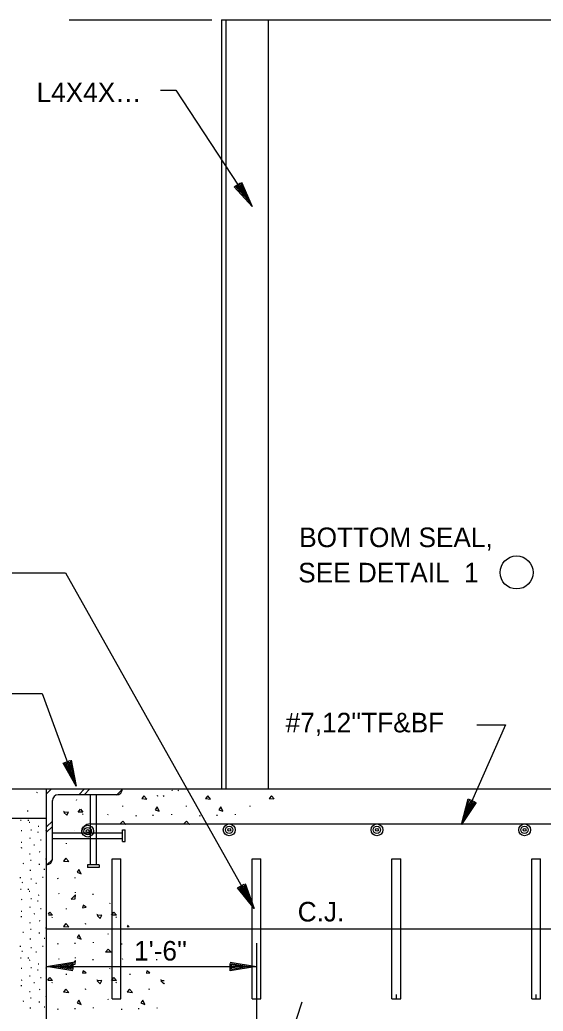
# Model space of a CAD drawing. Extents: x 0 to 320, y -4 to 473.
# Drawn here: x 22.92 to 26.66, y 15.08 to 22.17 of the extents above; entities that cross this region are included whole.
import ezdxf

# ---------------------------------------------------------------- set-up
doc = ezdxf.new("R2010")
doc.units = 0
for name, color, linetype in [('Level 10', 7, 'Continuous'), ('Level 2', 7, 'Continuous'), ('Level 25', 7, 'Continuous'), ('Level 3', 7, 'Continuous'), ('Level 44', 7, 'Continuous'), ('Level 50', 7, 'Continuous')]:
    doc.layers.add(name, color=color, linetype=linetype)

msp = doc.modelspace()

# ---------------------------------------------------------------- linework, layer by layer
at = {"layer": 'Level 10'}
for p, q in [((23.3282, 16.5926), (23.3305, 16.5975)), ((23.9093, 16.6204), (23.9065, 16.6259)), ((23.9538, 16.6204), (23.9509, 16.6259)), ((23.2382, 16.5126), (23.2387, 16.5171)), ((23.6587, 16.5478), (23.6582, 16.5529)), ((24.1142, 16.5478), (24.1138, 16.5529)), ((24.5697, 16.5478), (24.5693, 16.5529)), ((23.3713, 16.4917), (23.3744, 16.4969)), ((23.5527, 16.4893), (23.5536, 16.494)), ((23.7556, 16.4769), (23.7539, 16.4832)), ((23.8769, 16.4819), (23.8769, 16.4882)), ((24.0082, 16.4893), (24.0091, 16.494)), ((24.2112, 16.4769), (24.2094, 16.4832)), ((24.3324, 16.4819), (24.3324, 16.4882)), ((24.4638, 16.4893), (24.4646, 16.494)), ((23.3167, 16.375), (23.3167, 16.3755)), ((23.2558, 16.2809), (23.2567, 16.2869)), ((23.197, 16.0298), (23.1952, 16.0361)), ((23.3183, 16.0348), (23.3183, 16.0411)), ((23.2033, 15.922), (23.2015, 15.9265)), ((23.3204, 15.9312), (23.3204, 15.937)), ((23.4458, 15.9177), (23.4458, 15.924)), ((23.2558, 15.8133), (23.2567, 15.8193)), ((23.5667, 15.8552), (23.569, 15.8601)), ((23.1542, 15.7544), (23.1573, 15.7596)), ((23.4767, 15.7752), (23.4771, 15.7798)), ((23.6097, 15.7544), (23.6128, 15.7596)), ((23.3951, 15.7057), (23.3923, 15.7112)), ((23.5556, 15.6331), (23.5551, 15.6382)), ((23.197, 15.5622), (23.1952, 15.5685)), ((23.3183, 15.5672), (23.3183, 15.5735)), ((23.4496, 15.5746), (23.4504, 15.5793)), ((23.6525, 15.5622), (23.6508, 15.5685)), ((23.2033, 15.4544), (23.2015, 15.4589)), ((23.3204, 15.4636), (23.3204, 15.4694)), ((23.4458, 15.4501), (23.4458, 15.4564)), ((23.6588, 15.4544), (23.657, 15.4589)), ((23.9013, 15.4501), (23.9013, 15.4564)), ((23.5667, 15.3876), (23.569, 15.3925)), ((23.2558, 15.3457), (23.2567, 15.3517)), ((23.4767, 15.3076), (23.4771, 15.3122)), ((23.7113, 15.3457), (23.7122, 15.3517)), ((23.9322, 15.3076), (23.9326, 15.3122)), ((23.1542, 15.2868), (23.1573, 15.292)), ((23.3951, 15.2381), (23.3923, 15.2436)), ((23.6097, 15.2868), (23.6128, 15.292)), ((23.8507, 15.2381), (23.8478, 15.2436)), ((23.5556, 15.1654), (23.5551, 15.1706)), ((23.197, 15.0946), (23.1952, 15.1009)), ((23.3183, 15.0996), (23.3183, 15.1059)), ((23.4496, 15.107), (23.4504, 15.1117)), ((23.6525, 15.0946), (23.6508, 15.1009)), ((23.7738, 15.0996), (23.7738, 15.1059)), ((23.9051, 15.107), (23.906, 15.1117))]:
    msp.add_line(p, q, dxfattribs=at)
for points in [[(23.9293, 21.6715), (24.0386, 21.6715), (24.584, 20.8394)], [(24.0083, 16.6662), (24.0115, 16.6634), (24.013, 16.6662)], [(24.0528, 16.6662), (24.0559, 16.6634), (24.0574, 16.6662)], [(24.7401, 16.6038), (24.7214, 16.6254), (24.7048, 16.6057), (24.7377, 16.6021)], [(23.1274, 15.7787), (23.1383, 15.7931), (23.1571, 15.7717), (23.1274, 15.771)], [(23.6978, 15.6995), (23.6907, 15.691), (23.7048, 15.6894)], [(23.1235, 15.3059), (23.1383, 15.3254), (23.1571, 15.3041), (23.1235, 15.3033)], [(23.9538, 15.3025), (23.9307, 15.3009)], [(23.9307, 15.3009), (23.9528, 15.2811), (23.9563, 15.2876)]]:
    msp.add_lwpolyline(points, dxfattribs=at)
for points in [[(23.8309, 16.6016), (23.8103, 16.6254), (23.7938, 16.6057)], [(24.2865, 16.6016), (24.2658, 16.6254), (24.2493, 16.6057)], [(23.3386, 16.5082), (23.3553, 16.5304), (23.3742, 16.509)], [(23.8904, 16.5257), (23.9189, 16.5146), (23.9039, 16.5454)], [(24.3459, 16.5257), (24.3744, 16.5146), (24.3594, 16.5454)], [(23.2367, 16.5058), (23.2589, 16.486), (23.2707, 16.5082)], [(23.6382, 16.4227), (23.658, 16.4441), (23.6793, 16.4204)], [(24.0938, 16.4227), (24.1136, 16.4441), (24.1348, 16.4204)], [(23.2723, 16.1545), (23.2517, 16.1783), (23.2351, 16.1586)], [(23.3318, 16.0786), (23.3602, 16.0675), (23.3452, 16.0983)], [(23.3189, 15.8877), (23.3204, 15.9156), (23.2896, 15.8854)], [(23.3717, 15.8242), (23.397, 15.8274), (23.3758, 15.8417)], [(23.4751, 15.7685), (23.4973, 15.7487), (23.5092, 15.7709)], [(23.577, 15.7709), (23.5938, 15.7931), (23.6126, 15.7717)], [(23.2723, 15.6869), (23.2517, 15.7107), (23.2351, 15.691)], [(23.3318, 15.611), (23.3602, 15.5999), (23.3452, 15.6307)], [(23.5351, 15.5079), (23.5549, 15.5294), (23.5762, 15.5057)], [(23.3189, 15.4201), (23.3204, 15.4479), (23.2896, 15.4178)], [(23.3717, 15.3566), (23.397, 15.3598), (23.3758, 15.3741)], [(23.577, 15.3033), (23.5938, 15.3254), (23.6126, 15.3041)], [(23.8272, 15.3566), (23.8525, 15.3598), (23.8313, 15.3741)], [(23.2723, 15.2193), (23.2517, 15.2431), (23.2351, 15.2234)], [(23.4751, 15.3009), (23.4973, 15.2811), (23.5092, 15.3033)], [(23.7278, 15.2193), (23.7072, 15.2431), (23.6907, 15.2234)], [(23.3318, 15.1434), (23.3602, 15.1323), (23.3452, 15.1631)], [(23.7873, 15.1434), (23.8158, 15.1323), (23.8008, 15.1631)]]:
    msp.add_lwpolyline(points, close=True, dxfattribs=at)
at = {"layer": 'Level 2'}
for p, q in [((24.3641, 22.1736), (24.3641, 16.6736)), ((24.3641, 22.1736), (27.3641, 22.1736)), ((24.3953, 22.1736), (24.3953, 16.6736)), ((24.6974, 22.1736), (24.6974, 16.6736)), ((23.1141, 16.6379), (23.1497, 16.6736)), ((23.1141, 16.1319), (23.1141, 16.6736)), ((23.1141, 16.6736), (23.6558, 16.6736)), ((23.3438, 16.6319), (23.3854, 16.6736)), ((23.3815, 16.6319), (23.4231, 16.6736)), ((23.6172, 16.6319), (23.6589, 16.6736)), ((23.6558, 16.6736), (27.7755, 16.6736)), ((23.1558, 16.1736), (23.1558, 16.5903)), ((23.6141, 16.6319), (23.1974, 16.6319)), ((23.4266, 16.6319), (23.4266, 16.1319)), ((23.4683, 16.6319), (23.4683, 16.1319)), ((23.1141, 16.4022), (23.1558, 16.4439)), ((23.1141, 16.3645), (23.1558, 16.4062)), ((23.6558, 16.2986), (23.6558, 16.3819)), ((23.6558, 16.3819), (23.6766, 16.3819)), ((23.6766, 16.2986), (23.6766, 16.3819)), ((23.1558, 16.3611), (23.6558, 16.3611)), ((23.1558, 16.3194), (23.6558, 16.3194)), ((23.6558, 16.2986), (23.6766, 16.2986)), ((23.1141, 16.1288), (23.1558, 16.1705)), ((23.5828, 15.1736), (23.5828, 16.1736)), ((23.6453, 15.1736), (23.6453, 16.1736)), ((24.5828, 15.1736), (24.5828, 16.1736)), ((24.6453, 15.1736), (24.6453, 16.1736)), ((25.5828, 15.1736), (25.5828, 16.1736)), ((25.6453, 15.1736), (25.6453, 16.1736)), ((26.5828, 15.1736), (26.5828, 16.1736)), ((26.6453, 15.1736), (26.6453, 16.1736)), ((23.1141, 13.8403), (23.1141, 16.1319)), ((23.4891, 16.1319), (23.4058, 16.1319)), ((23.4058, 16.1319), (23.4058, 16.1111)), ((23.4891, 16.1111), (23.4058, 16.1111)), ((23.4891, 16.1319), (23.4891, 16.1111)), ((23.1141, 15.6736), (33.1141, 15.6736)), ((24.6141, 15.5702), (24.6141, 11.3263)), ((25.6141, 15.1736), (25.6141, 15.2048)), ((26.6141, 15.1736), (26.6141, 15.2048))]:
    msp.add_line(p, q, dxfattribs=at)
for centre, start, end in [((23.6141, 16.6736), 270, 359.99999), ((23.1974, 16.5903), 90, 180), ((23.1141, 16.1736), 270, 0)]:
    msp.add_arc(centre, 0.0417, start, end, dxfattribs=at)
at = {"layer": 'Level 25'}
msp.add_line((24.9394, 15.1497), (23.841, 11.8543), dxfattribs=at)
msp.add_circle((26.4737, 18.2219), 0.118, dxfattribs=at)
at = {"layer": 'Level 3'}
for p, q in [((23.2746, 22.1733), (24.2949, 22.1733)), ((23.3076, 16.7423), (23.3076, 16.7423)), ((19.7972, 16.6736), (23.1141, 16.6736)), ((23.3256, 16.6935), (23.3256, 16.6935)), ((19.7972, 16.4653), (23.1141, 16.4653)), ((22.9327, 16.4481), (22.9271, 16.4477)), ((22.9872, 16.4481), (22.9809, 16.4481)), ((26.1013, 16.467), (26.1013, 16.467)), ((22.9949, 16.4334), (22.9894, 16.4331)), ((23.0059, 16.3803), (23.0004, 16.3798)), ((23.0592, 16.4059), (23.0537, 16.4054)), ((23.1141, 16.3779), (23.1081, 16.3788)), ((23.4266, 16.4236), (32.8016, 16.4236)), ((26.0804, 16.4194), (26.0804, 16.4194)), ((22.9382, 16.3748), (22.9327, 16.3743)), ((22.9971, 16.3211), (22.9923, 16.3192)), ((23.0537, 16.3637), (23.0482, 16.3633)), ((23.0757, 16.3087), (23.0702, 16.3083)), ((22.9362, 16.2518), (22.9307, 16.2513)), ((22.9382, 16.2904), (22.9327, 16.2899)), ((23.0281, 16.2721), (23.0226, 16.2716)), ((22.9968, 16.2078), (22.9912, 16.2073)), ((23.0692, 16.2217), (23.0639, 16.2242)), ((23.1124, 16.1712), (23.1069, 16.1707)), ((22.9491, 16.1399), (22.9436, 16.1396)), ((23.0042, 16.1619), (22.9987, 16.1614)), ((23.0647, 16.1344), (23.0592, 16.1341)), ((23.1014, 16.0978), (23.0943, 16.0972)), ((22.9289, 16.0391), (22.9234, 16.0386)), ((23.0017, 16.0911), (22.9949, 16.0911)), ((23.0059, 16.0298), (23.0004, 16.0294)), ((23.0903, 16.0408), (23.0848, 16.0404)), ((22.9327, 15.9557), (22.9271, 15.9553)), ((22.9417, 16.0042), (22.9362, 16.0037)), ((22.9872, 15.9557), (22.9809, 15.9557)), ((23.0427, 15.9987), (23.0372, 15.9982)), ((22.9382, 15.8824), (22.9327, 15.8819)), ((22.9949, 15.9411), (22.9894, 15.9407)), ((23.0059, 15.8879), (23.0004, 15.8874)), ((23.0592, 15.9136), (23.0537, 15.9131)), ((23.1141, 15.8855), (23.1081, 15.8864)), ((22.9971, 15.8287), (22.9923, 15.8268)), ((23.0537, 15.8713), (23.0482, 15.8709)), ((23.0757, 15.8163), (23.0702, 15.8159)), ((24.5725, 15.865), (24.5725, 15.865)), ((24.598, 15.8197), (24.598, 15.8197)), ((22.9362, 15.7594), (22.9307, 15.7589)), ((22.9382, 15.7981), (22.9327, 15.7976)), ((23.0281, 15.7797), (23.0226, 15.7792)), ((22.9968, 15.7154), (22.9912, 15.7149)), ((23.0042, 15.6696), (22.9987, 15.6691)), ((23.0692, 15.7293), (23.0639, 15.7318)), ((23.1124, 15.6788), (23.1069, 15.6783)), ((22.9491, 15.6476), (22.9436, 15.6472)), ((23.0017, 15.5987), (22.9949, 15.5987)), ((23.0647, 15.6421), (23.0592, 15.6417)), ((23.1014, 15.6054), (23.0958, 15.6049)), ((22.9289, 15.5467), (22.9234, 15.5462)), ((23.0059, 15.5374), (23.0004, 15.5371)), ((23.0903, 15.5484), (23.0848, 15.5481)), ((22.9327, 15.4633), (22.9271, 15.4629)), ((22.9417, 15.5118), (22.9362, 15.5113)), ((22.9872, 15.4633), (22.9809, 15.4633)), ((23.0427, 15.5063), (23.0372, 15.5058)), ((22.9382, 15.3901), (22.9327, 15.3896)), ((22.9949, 15.4487), (22.9894, 15.4483)), ((23.0059, 15.3956), (23.0004, 15.3951)), ((23.0592, 15.4212), (23.0537, 15.4207)), ((23.1141, 15.3931), (23.1081, 15.3941)), ((23.1141, 15.4047), (24.6141, 15.4047)), ((22.9971, 15.3363), (22.9923, 15.3344)), ((23.0537, 15.3789), (23.0482, 15.3786)), ((23.0757, 15.3239), (23.0702, 15.3236)), ((22.9362, 15.2671), (22.9307, 15.2666)), ((22.9382, 15.3057), (22.9327, 15.3052)), ((23.0281, 15.2873), (23.0226, 15.2868)), ((22.9968, 15.2231), (22.9912, 15.2226)), ((23.0042, 15.1772), (22.9987, 15.1767)), ((23.0692, 15.2369), (23.0639, 15.2394)), ((23.1124, 15.1864), (23.1069, 15.1859)), ((22.9491, 15.1552), (22.9436, 15.1548)), ((23.0017, 15.1063), (22.9949, 15.1063)), ((23.0647, 15.1497), (23.0592, 15.1493)), ((23.1014, 15.1131), (23.0958, 15.1126))]:
    msp.add_line(p, q, dxfattribs=at)
for points in [[(22.7059, 18.2184), (23.2482, 18.2184), (24.598, 15.8197)], [(22.8151, 17.3553), (23.0825, 17.3553), (23.3256, 16.6935)], [(26.1889, 17.1322), (26.3938, 17.1322), (26.0804, 16.4194)], [(23.2902, 16.8797), (23.3256, 16.6935), (23.232, 16.8583), (23.2817, 16.8766), (23.3076, 16.7423), (23.2441, 16.8542), (23.2761, 16.866), (23.2904, 16.7892), (23.2563, 16.8502), (23.2694, 16.855), (23.2725, 16.838)], [(26.184, 16.5781), (26.0804, 16.4194), (26.1273, 16.603), (26.1758, 16.5817), (26.1013, 16.467), (26.1332, 16.5917), (26.1643, 16.578), (26.1214, 16.5127), (26.1391, 16.5803), (26.152, 16.5747), (26.1424, 16.5603)], [(24.5333, 15.9979), (24.598, 15.8197), (24.4793, 15.9674), (24.5255, 15.9934), (24.5725, 15.865), (24.4919, 15.9654), (24.5216, 15.9821), (24.548, 15.9086), (24.5046, 15.9633), (24.5168, 15.9702), (24.5225, 15.9539)]]:
    msp.add_lwpolyline(points, dxfattribs=at)
msp.add_arc((23.4266, 16.3611), 0.0625, 90, 180, dxfattribs=at)
at = {"layer": 'Level 44'}
for p, q in [((23.0496, 16.6456), (23.0443, 16.6481)), ((22.9821, 16.515), (22.9754, 16.515)), ((23.5828, 16.1736), (23.6453, 16.1736)), ((24.5828, 16.1736), (24.6453, 16.1736)), ((25.5828, 16.1736), (25.6453, 16.1736)), ((26.5828, 16.1736), (26.6453, 16.1736)), ((23.5828, 15.1736), (23.6453, 15.1736)), ((24.5828, 15.1736), (24.6453, 15.1736)), ((25.5828, 15.1736), (25.6453, 15.1736)), ((26.5828, 15.1736), (26.6453, 15.1736))]:
    msp.add_line(p, q, dxfattribs=at)
at = {"layer": 'Level 50'}
for p, q in [((24.5555, 20.8829), (24.5555, 20.8829)), ((24.584, 20.8394), (24.584, 20.8394)), ((23.1141, 15.4047), (23.1141, 15.4047)), ((23.1661, 15.4047), (23.1661, 15.4047)), ((24.5621, 15.4047), (24.5621, 15.4047)), ((24.6141, 15.4047), (24.6141, 15.4047))]:
    msp.add_line(p, q, dxfattribs=at)
for points in [[(24.5074, 21.0128), (24.584, 20.8394), (24.4556, 20.9788), (24.4999, 21.0079), (24.5555, 20.8829), (24.4683, 20.9776), (24.4968, 20.9962), (24.5281, 20.9247), (24.4811, 20.9764), (24.4928, 20.9841), (24.4996, 20.9682)], [(23.3011, 15.3737), (23.1141, 15.4047), (23.3011, 15.4357), (23.3011, 15.3827), (23.1661, 15.4047), (23.2931, 15.4257), (23.2931, 15.3917), (23.2161, 15.4047), (23.2851, 15.4157), (23.2851, 15.4017), (23.2681, 15.4047)], [(24.4271, 15.4357), (24.6141, 15.4047), (24.4271, 15.3737), (24.4271, 15.4267), (24.5621, 15.4047), (24.4351, 15.3837), (24.4351, 15.4177), (24.5121, 15.4047), (24.4431, 15.3937), (24.4431, 15.4077), (24.4601, 15.4047)]]:
    msp.add_lwpolyline(points, dxfattribs=at)
for centre, radius in [((23.4077, 16.3723), 0.0422), ((23.4077, 16.3723), 0.0264), ((23.4077, 16.3723), 0.0105), ((24.4196, 16.3814), 0.0422), ((24.4196, 16.3814), 0.0264), ((24.4196, 16.3814), 0.0105), ((25.4752, 16.3814), 0.0422), ((25.4752, 16.3814), 0.0264), ((25.4752, 16.3814), 0.0105), ((26.5308, 16.3814), 0.0422), ((26.5308, 16.3814), 0.0264), ((26.5308, 16.3814), 0.0105)]:
    msp.add_circle(centre, radius, dxfattribs=at)

# ---------------------------------------------------------------- texts
at = {"layer": 'Level 10'}
msp.add_text('L4X4X…', height=0.14, dxfattribs=at).set_placement((23.0427, 21.5852))
at = {"layer": 'Level 3'}
for s, p in [('BOTTOM SEAL,', (24.9197, 18.403)), ('SEE DETAIL  1', (24.9127, 18.1509)), ("#7,12''TF&BF", (24.8231, 17.0785)), ('C.J.', (24.9091, 15.7261)), ("1'-6''", (23.7399, 15.4468))]:
    msp.add_text(s, height=0.14, dxfattribs=at).set_placement(p)

doc.saveas('drawing.dxf')
